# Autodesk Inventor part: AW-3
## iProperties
Author: w30cdbam
Shininess: 64.0
Angle Display Precision: 2
Document Length Units: 11272
Document Angle Units: 11286
Document Time Units: 11279
Document Mass Units: 11290
Document Length Units Precision: 3
Document Angle Units Precision: 2
Compacted: True
PropertySet Name: _Private Model Information
Created: 2001-12
Part Number: AW-3
Material: Stainless Steel, Austenitic
Description: Rod End - #10 Female
Document SubType Name: Modeling
Designer: w30cdbam
Control State: 0
Master: False
Checked Out: False
PropertySet Name: Design Tracking Control
Density: 0.0
Volumn: 0.0
Area: 0.0
PropertySet Name: Model Information
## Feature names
1. Revolution1
2. Extrusion1
3. Revolution2
4. Revolution3
5. Revolution5
6. Extrusion2
7. Mirror1
8. Fillet2
9. Fillet3
10. Extrusion3
11. Extrusion4
12. Fillet4
